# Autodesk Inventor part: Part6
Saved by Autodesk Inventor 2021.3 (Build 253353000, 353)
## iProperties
Created: 2022-12
Part Number: Part6
Material: Generic
Document SubType Name: Modeling
Designer: Administrator
Density: 1 g/cm^3
Appearance: Default
Author: Administrator
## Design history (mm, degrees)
feature "Body1"
body "Solid1"
